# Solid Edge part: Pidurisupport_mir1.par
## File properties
Author: Türk
Template: Iso Part.par
Last saved by: Türk
Revision: 2
Application: Solid Edge
Accuracy: 0,990
Username: Türk
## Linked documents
Pidurisupport.par
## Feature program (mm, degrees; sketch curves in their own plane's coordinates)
part copy "CopiedPart_1"
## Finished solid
Body 1: solid body, 63 faces, 128 edges, 66 vertices.
  Faces by surface: plane 27, cylinder 22, cone 13, spline 1
  Edges by curve: circle 64, line 40, intersection 10, ellipse 8, curve on surface 6
Bounding box of the edges (mm; curved faces can reach further): 96.748 x 162.000 x 85.456, from (-27.7472, -80, -26.5) to (69.0008, 82, 58.9555).
Cylindrical faces by radius (mm): R4 x8, R5 x2, R10 x6, R12.5 x3, R60 x2, R100 x1
Conical faces (half-angle, radius in mm at the cone's reference point): 45 deg R5 x2, 45 deg R12.5 x6, 45 deg R60 x1, 45 deg R61 x2, 45 deg R99 x1, 45 deg R100 x1
Planar faces by outward normal: +x 2, +y 8, -y 7, -z 2, oblique 8
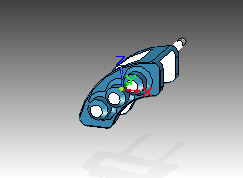
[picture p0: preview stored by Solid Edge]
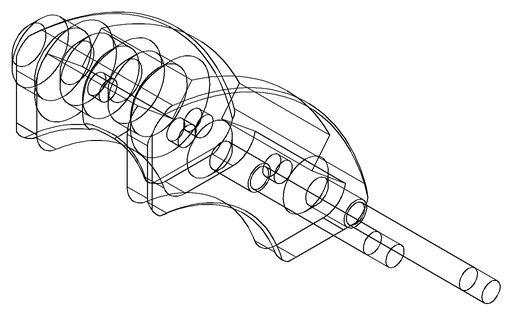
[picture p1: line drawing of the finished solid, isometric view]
